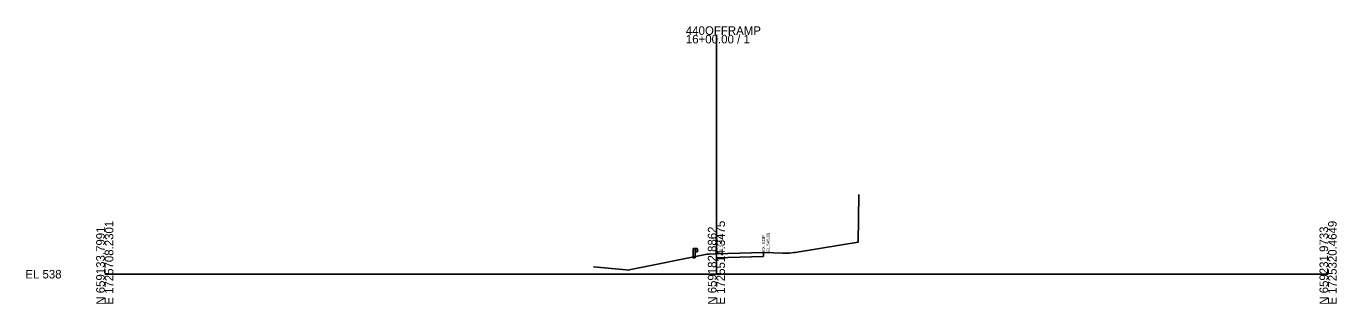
# Model space of a CAD drawing. Extents: x 1728898 to 1729326, y 661368 to 668397.
# Drawn here: x 1728897.8 to 1729326.3, y 662868.4 to 662959.3 of the extents above; entities that cross this region are included whole.
import ezdxf

# ---------------------------------------------------------------- set-up
doc = ezdxf.new("R2010")
doc.units = 0
for name, color, linetype in [('DESIGN - SHEET - Light Grid', 7, 'Continuous'), ('DESIGN - TYPICAL - Guardrail', 7, 'Continuous'), ('SURVEY - GROUND - Existing Pavement Layer', 7, 'Continuous'), ('SURVEY - GROUND - Existing Pavement Text', 7, 'Continuous'), ('SURVEY - GROUND - Top of Ground', 7, 'Continuous')]:
    doc.layers.add(name, color=color, linetype=linetype)

msp = doc.modelspace()

# ---------------------------------------------------------------- linework, layer by layer
at = {"layer": 'DESIGN - SHEET - Light Grid'}
for p, q in [((1729123.44, 662878.11), (1729123.44, 662956.44)), ((1728923.44, 662878.11), (1729123.44, 662878.11)), ((1729123.44, 662878.11), (1729323.44, 662878.11))]:
    msp.add_line(p, q, dxfattribs=at)
at = {"layer": 'DESIGN - TYPICAL - Guardrail'}
for p, q in [((1729115.82, 662886.56), (1729115.82, 662883.91)), ((1729116.49, 662886.56), (1729115.82, 662886.56)), ((1729116.49, 662886.56), (1729117.11, 662886.56)), ((1729116.49, 662883.91), (1729116.49, 662886.56)), ((1729117.11, 662885.4), (1729116.49, 662885.4)), ((1729117.11, 662886.56), (1729117.11, 662885.4)), ((1729117.11, 662886.49), (1729117.2, 662886.44)), ((1729117.15, 662886.08), (1729117.11, 662886.02)), ((1729117.11, 662886.02), (1729117.11, 662885.98)), ((1729117.11, 662885.98), (1729117.11, 662885.94)), ((1729117.11, 662885.94), (1729117.15, 662885.88)), ((1729117.2, 662885.52), (1729117.11, 662885.47)), ((1729117.35, 662886.2), (1729117.15, 662886.08)), ((1729117.15, 662885.88), (1729117.35, 662885.76)), ((1729117.2, 662886.44), (1729117.35, 662886.31)), ((1729117.35, 662885.65), (1729117.2, 662885.52)), ((1729117.35, 662886.31), (1729117.38, 662886.26)), ((1729117.38, 662886.26), (1729117.35, 662886.2)), ((1729117.35, 662885.76), (1729117.38, 662885.7)), ((1729117.38, 662885.7), (1729117.35, 662885.65)), ((1729115.82, 662883.35), (1729115.82, 662883.91)), ((1729116.07, 662883.45), (1729115.82, 662883.35)), ((1729116.32, 662883.41), (1729116.07, 662883.45)), ((1729116.49, 662883.45), (1729116.32, 662883.41)), ((1729116.49, 662883.91), (1729116.49, 662883.45))]:
    msp.add_line(p, q, dxfattribs=at)
at = {"layer": 'SURVEY - GROUND - Existing Pavement Layer'}
for p, q in [((1729123.48, 662883.48), (1729123.48, 662884.73)), ((1729138.83, 662885.19), (1729138.83, 662883.94)), ((1729123.48, 662883.48), (1729127.17, 662883.59)), ((1729127.17, 662883.59), (1729138.83, 662883.94))]:
    msp.add_line(p, q, dxfattribs=at)
at = {"layer": 'SURVEY - GROUND - Top of Ground'}
msp.add_lwpolyline([(1729083.26, 662880.54), (1729093.9, 662879.48), (1729094.53, 662879.42), (1729095.47, 662879.61), (1729120.41, 662884.63), (1729121.19, 662884.66), (1729123.48, 662884.73), (1729127.17, 662884.84), (1729138.83, 662885.19), (1729145.13, 662885.04), (1729147.38, 662884.98), (1729148.74, 662885.18), (1729149.22, 662885.25), (1729164.49, 662887.75), (1729169.79, 662888.62), (1729170.05, 662904.22)], dxfattribs=at)

# ---------------------------------------------------------------- texts
at = {"layer": 'DESIGN - SHEET - Light Grid'}
for s, p in [('440OFFRAMP', (1729113.44, 662956.44)), ('16+00.00 / 1', (1729113.44, 662953.64)), ('EL 538', (1728897.44, 662876.71))]:
    msp.add_text(s, height=2.8, dxfattribs=at).set_placement(p)
for s, p in [('N 659133.7991', (1728923.44, 662868.11)), ('E 1725708.2301', (1728926.24, 662868.11)), ('N 659182.8862', (1729123.44, 662868.11)), ('E 1725514.3475', (1729126.24, 662868.11)), ('N 659231.9733', (1729323.44, 662868.11)), ('E 1725320.4649', (1729326.24, 662868.11))]:
    msp.add_text(s, height=2.8, rotation=90, dxfattribs=at).set_placement(p)
at = {"layer": 'SURVEY - GROUND - Existing Pavement Text'}
for s, p in [('EX. EOP', (1729123.98, 662884.93)), ('EL.544.63', (1729125.48, 662884.93)), ('EX. EOP', (1729139.33, 662885.39)), ('EL.545.09', (1729140.83, 662885.39))]:
    msp.add_text(s, height=1, rotation=90, dxfattribs=at).set_placement(p)

doc.saveas('drawing.dxf')
